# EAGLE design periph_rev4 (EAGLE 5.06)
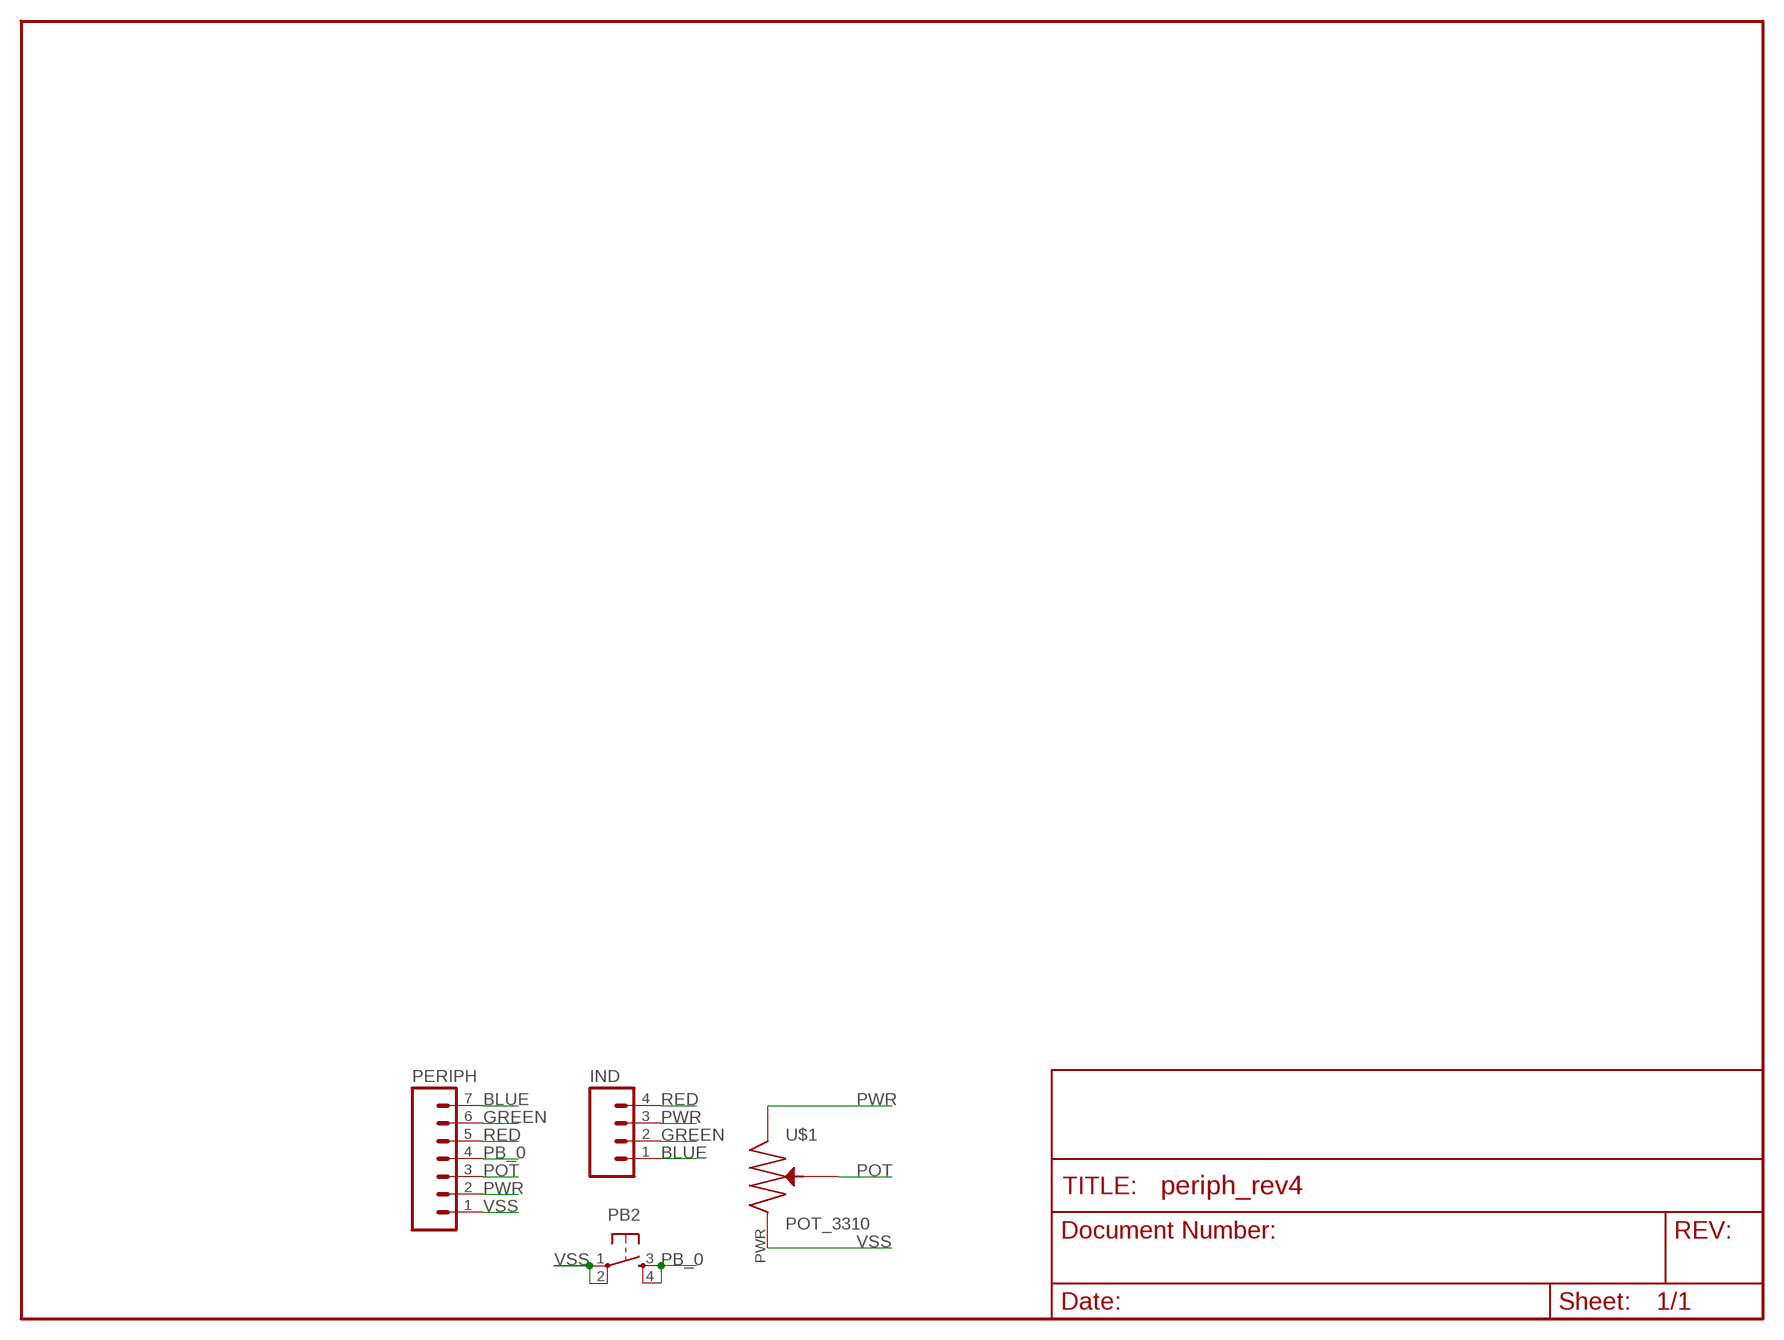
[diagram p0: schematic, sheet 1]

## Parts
IND  M04PTH  [1X04]
PB2  TAC_SWITCHPTH  [TACTILE-PTH]
PERIPH  M07  [1X07]
U$1  POT_3310  [POT_TRIM]

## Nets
BLUE: IND.1 PERIPH.7
GREEN: IND.2 PERIPH.6
PB_0: PB2.3 PB2.4 PERIPH.4
POT: PERIPH.3 U$1.POT
PWR: IND.3 PERIPH.2 U$1.GND(SUPPLY1)
RED: IND.4 PERIPH.5
VSS: PB2.1 PB2.2 PERIPH.1 U$1.PWR(SUPPLY2)

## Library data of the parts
IND = SparkFun:M04: Header 4 Standard 4-pin 0.1" header. Use with straight break away headers (SKU : PRT-00116), right angle break away headers (PRT-00553), swiss pins (PRT-00743), machine pins (PRT-00117), and female headers (PRT-00115). Molex polarized connector foot print use with SKU : PRT-08231 with associated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
PB2 = SparkFun:TAC_SWITCH: Momentary Switch Button commonly used for reset or general input. Spark Fun Electronics SKU : COM-00097
PERIPH = SparkFun:M07: Header 7 Standard 7-pin 0.1" header. Use with straight break away headers (SKU : PRT-00116), right angle break away headers (PRT-00553), swiss pins (PRT-00743), machine pins (PRT-00117), and female headers (PRT-00115). NOTES ON THE VARIANTS LOCK and LOCK_LONGPADS... This footprint was designed to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
U$1 = NBitWonder:POT_3310: Square 9mm plastic potentiometer part

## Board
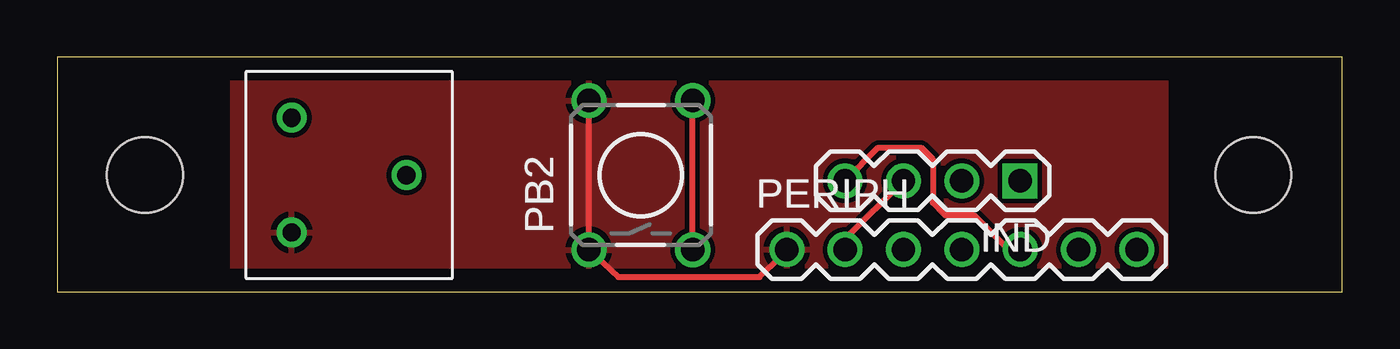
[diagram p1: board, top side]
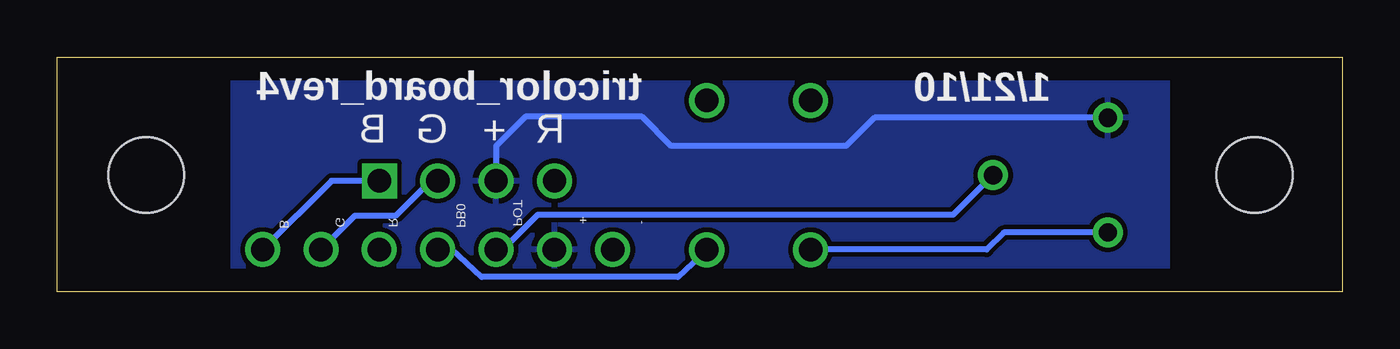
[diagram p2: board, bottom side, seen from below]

Size 55.93 x 10.21 mm. Coordinates in mm from the lower left corner, seen from the top.
Outline: 0,0 55.93,0 55.93,10.21 0,10.21 0,0
Copper layers (1*16): Top 0.035mm / dielectric 1.5mm / Bottom 0.035mm
Design rules "default": minimum track width 10mil, minimum drill 24mil, track to track 8mil, track to pad 8mil, pad to pad 8mil, via to via 8mil, smd to smd 8mil, copper to edge 40mil, drill to drill 8mil, minimum pad ring 10mil, minimum via ring 8mil, stop-mask expansion 4mil, vias tented up to drill 0mil, thermal gap 10mil

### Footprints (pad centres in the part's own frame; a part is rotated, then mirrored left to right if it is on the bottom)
1X04 = drill 1.016 square: 1 0,0 | drill 1.016 round: 2 2.54,0; 3 5.08,0; 4 7.62,0
TACTILE-PTH = drill 1.016 round: 1 -3.251,2.261; 2 3.251,2.261; 3 -3.251,-2.261; 4 3.251,-2.261
1X07 = drill 1.016 round: 1 0,0; 2 2.54,0; 3 5.08,0; 4 7.62,0; 5 10.16,0; 6 12.7,0; 7 15.24,0
POT_TRIM = drill 0.8 round: GND 2.5,-2.5; POT -2.5,0; PWR 2.5,2.5
STAND-OFF = hole 3.302: 0,0

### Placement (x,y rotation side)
IND  41.91,4.83 180 top
PB2  25.4,5.08 90 top
PERIPH  31.75,1.83 0 top
U$1  12.7,5.08 180 top
U$5  [STAND-OFF]  3.81,5.08 90 top
U$6  [STAND-OFF]  52.07,5.08 0 top

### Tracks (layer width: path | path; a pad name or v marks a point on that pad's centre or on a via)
BLUE
  Bottom 0.254: IND.1 43.99,4.83 PERIPH.7
GREEN
  Bottom 0.254: IND.2 39.68,4.83 41.21,3.3 42.98,3.3 PERIPH.6
PB_0
  Top 0.254: PB2.3 PB2.4
  Bottom 0.254: PERIPH.4 38.76,1.83 37.45,0.64 28.92,0.64 PB2.3
POT
  Bottom 0.254: PERIPH.3 36.53,1.83 35.02,3.35 16.93,3.35 U$1.POT
PWR
  Top 0.254: PERIPH.2 34.3,2.29 IND.3
  Bottom 0.254: U$1.GND 20.36,7.58 21.59,6.35 29.21,6.35 30.48,7.62 35.56,7.62 36.83,6.35 IND.3
  pour Bottom: 7.62,10.16 7.62,0 48.26,0 48.26,10.16
RED
  Top 0.254: PERIPH.5 41.41,1.83 39.9,3.34 38.65,3.34 38.11,3.88 38.11,5.78 37.62,6.27 35.73,6.27 IND.4
VSS
  Top 0.254: PERIPH.1 31.75,1.76 30.57,0.64 24.41,0.64 PB2.1 PB2.2
  Bottom 0.254: U$1.PWR 14.73,2.58 15.47,1.83 PB2.1
  pour Top: 7.62,10.16 7.62,0 48.26,0 48.26,10.16

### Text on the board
bPlace: 1/21/10 | tricolor_board_rev4 | R | + | G | B | - | + | POT | PB0 | R | G | B
_tNames: PERIPH | PERIPH | PB2 | PB2 | IND | IND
